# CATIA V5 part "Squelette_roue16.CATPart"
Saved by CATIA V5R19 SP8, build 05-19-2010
Part number: Squelette_roue16
Bounding box of the stored display mesh (mm): x -15 to 5, y 0 to 30, z 30 to 30
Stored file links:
  G:\EU_thinkMotion\CFAO_2010\MMS_groupe2\MMS_groupe2\A reprendre\jcauchy\Squelette_roue16.CATPart
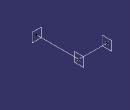
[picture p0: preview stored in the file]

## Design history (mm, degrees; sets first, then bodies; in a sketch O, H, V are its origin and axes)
Parameters
  Longueurfixation_roue16 = 20 mm
  Rayonroue_roue16 = 30 mm
Set1
  Point1: (5 {= Longueurfixation_roue16 -15mm}, 30, 30)
  Point2: (-15, 30, 30)
  Line1: type PtPt, FirstPoint Point1, SecondPoint Point2
  Plane1: type Normal, Curve Line1, RefPoint Point2
  Plane2: type Normal, Curve Line1, RefPoint Point1
  Point3: type OnCurve, Support Line1, RefPoint Point2, Length -20 {= -Longueurfixation_roue16}
  Line2: type Angle, RefPoint Point3, Curve Line1, Support xy-plane, Start 0, End 30 {= Rayonroue_roue16}, Angle 90
  Plane3: type Normal, Curve Line2, RefPoint vertex of Line2
Body1 (main body)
